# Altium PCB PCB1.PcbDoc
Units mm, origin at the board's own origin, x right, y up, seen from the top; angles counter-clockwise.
Board outline 46 x 20 mm, 2 copper layers (Top Layer, Bottom Layer), stack 1.57 mm thick; 25 components, 17 nets, 41 pads, 5 vias.
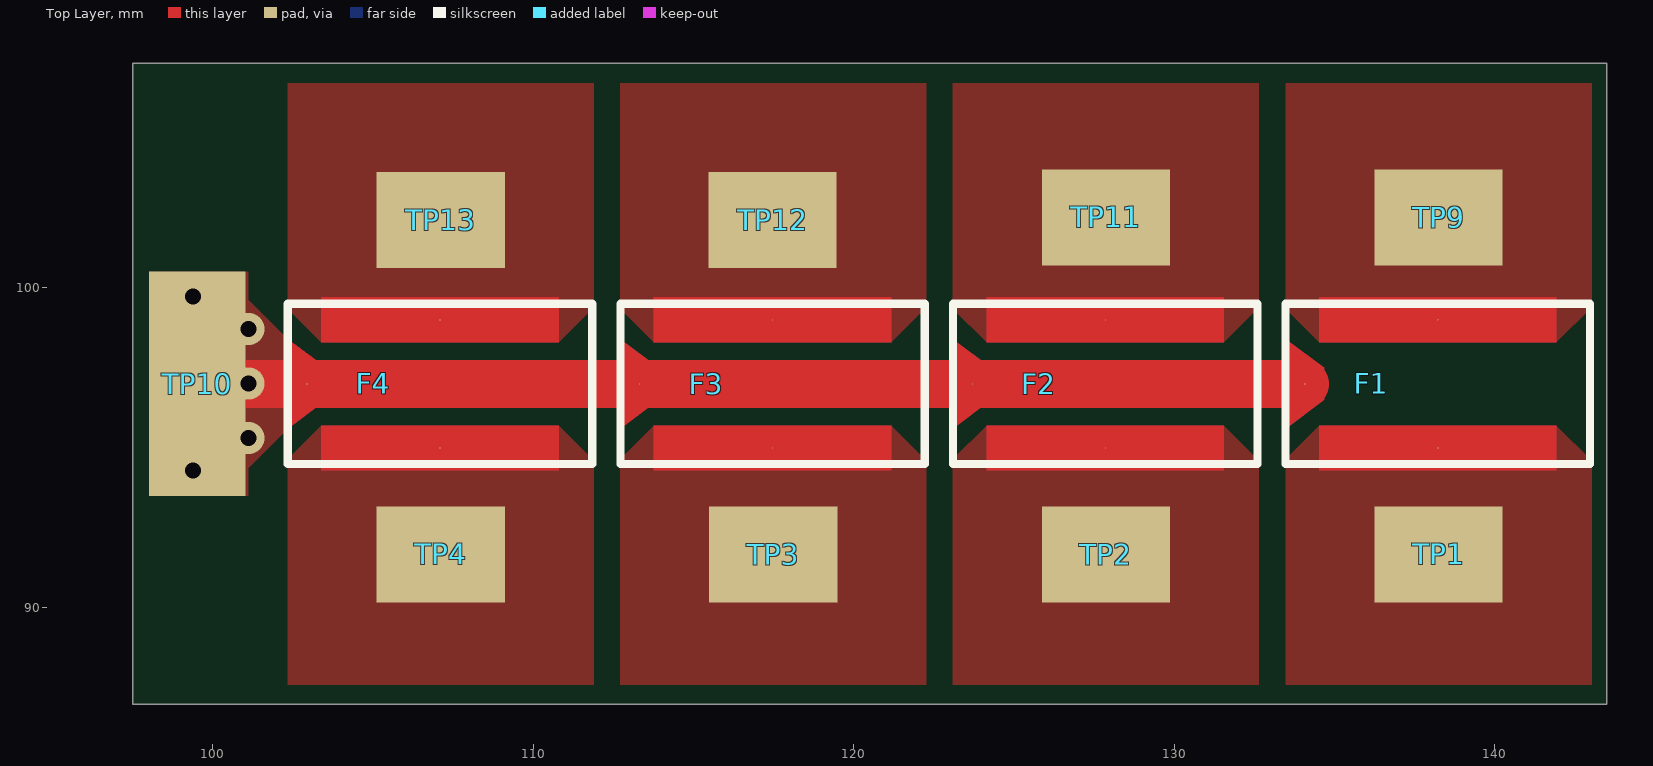
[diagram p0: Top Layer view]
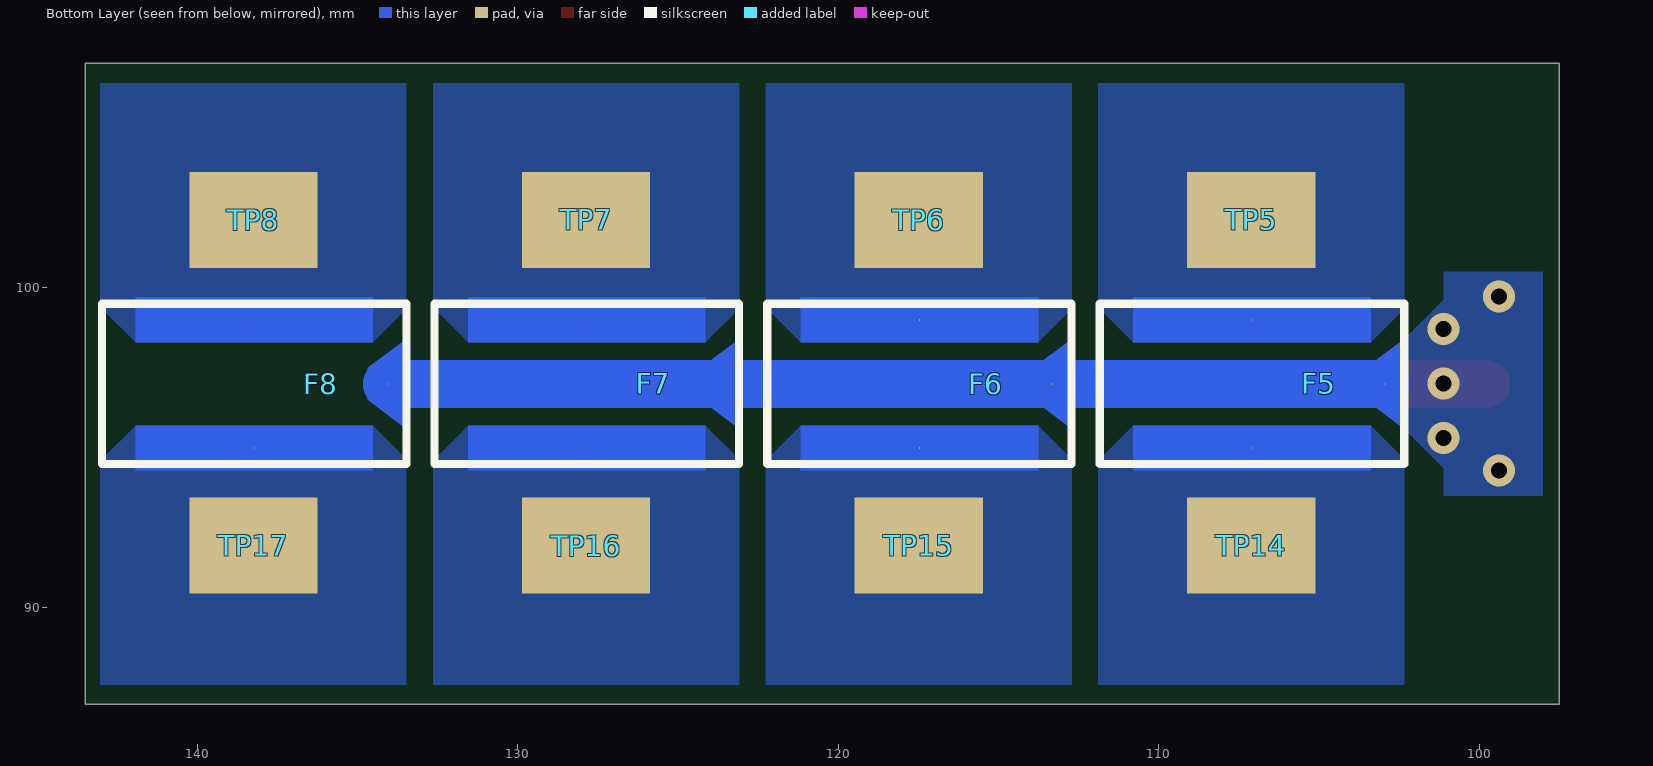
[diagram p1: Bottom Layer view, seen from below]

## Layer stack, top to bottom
Top Solder: solder mask 0.0102, Solder Resist, Dk 3.5
Top Layer: signal copper 0.035
Dielectric 1: core 1.5, FR-4, Dk 4.8
Bottom Layer: signal copper 0.035
Bottom Solder: solder mask 0.0102, Solder Resist, Dk 3.5

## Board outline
97.5,87 97.5,107 143.5,107 143.5,87

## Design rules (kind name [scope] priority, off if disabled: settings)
Clearance [All] p1: gap=0.254 ignorepadtopadclearanceinfootprint=FALSE except(0: Arc-Hole Track-Hole SMDPad-Hole THPad-Hole Via-Hole Fill-Hole Poly-Hole Region-Hole Text-Hole)
MinimumSolderMaskSliver [All] p1: minsoldermaskwidth=0
PolygonConnect [All] p1: connectstyle=Direct reliefconductorwidth=0.254 reliefentries=4 polygonreliefangle="90 Angle" airgapwidth=0.254
RoutingVias [All] p1: holewidth=0.5 width=1 viastyle="Through Hole" minholewidth=0.5 minwidth=1 maxholewidth=0.5 maxwidth=1
SilkToSilkClearance [All] p1: silktosilkclearance=0.127
SilkToSolderMaskClearance [IsPad] p1: minsilkscreentomaskgap=0 clearancetoexposedcopper=TRUE
SolderMaskExpansion [All] p1: expansion=0.102 istentingtop=FALSE
UnRoutedNet [All] p1: checkbadconnections=TRUE
Width [All] p1: maxlimit=5 minlimit=0.254 preferedwidth=0.254 minimp=50.000000 maximp=50.000000 favimp=50.000000
26 further rules are at their usual default settings.

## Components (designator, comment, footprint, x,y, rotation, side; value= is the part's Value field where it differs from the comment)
F1 "SCP60A4K" SCP60a4k 138.225,96.99 r0 top
F2 "SCP60A4K" SCP60a4k 127.846,96.99 r0 top
F3 "SCP60A4K" SCP60a4k 117.468,96.99 r0 top
F4 "SCP60A4K" SCP60a4k 107.089,96.99 r0 top
F5 "SCP60A4K" SCP60a4k 107.089,96.99 r0 bottom
F6 "SCP60A4K" SCP60a4k 117.468,96.99 r0 bottom
F7 "SCP60A4K" SCP60a4k 127.846,96.99 r0 bottom
F8 "SCP60A4K" SCP60a4k 138.225,96.99 r0 bottom
TP1 "3x4mm Test Pad SMD" "3x4mm Test Pad SMD" 138.248,91.669 r90 top
TP2 "3x4mm Test Pad SMD" "3x4mm Test Pad SMD" 127.869,91.669 r90 top
TP3 "3x4mm Test Pad SMD" "3x4mm Test Pad SMD" 117.49,91.669 r90 top
TP4 "3x4mm Test Pad SMD" "3x4mm Test Pad SMD" 107.112,91.669 r90 top
TP5 "3x4mm Test Pad SMD" "3x4mm Test Pad SMD" 107.112,102.108 r270 bottom
TP6 "3x4mm Test Pad SMD" "3x4mm Test Pad SMD" 117.49,102.108 r270 bottom
TP7 "3x4mm Test Pad SMD" "3x4mm Test Pad SMD" 127.869,102.108 r270 bottom
TP8 "3x4mm Test Pad SMD" "3x4mm Test Pad SMD" 138.248,102.108 r270 bottom
TP9 "3x4mm Test Pad SMD" "3x4mm Test Pad SMD" 138.248,102.184 r90 top
TP10 "10X10MM TEST PAD SMD" "10X10MM TEST PAD SMD" 99.517,96.997 r270 top
TP11 "3x4mm Test Pad SMD" "3x4mm Test Pad SMD" 127.869,102.184 r90 top
TP12 "3x4mm Test Pad SMD" "3x4mm Test Pad SMD" 117.468,102.108 r90 top
TP13 "3x4mm Test Pad SMD" "3x4mm Test Pad SMD" 107.112,102.108 r90 top
TP14 "3x4mm Test Pad SMD" "3x4mm Test Pad SMD" 107.112,91.948 r90 bottom
TP15 "3x4mm Test Pad SMD" "3x4mm Test Pad SMD" 117.49,91.948 r270 bottom
TP16 "3x4mm Test Pad SMD" "3x4mm Test Pad SMD" 127.869,91.948 r270 bottom
TP17 "3x4mm Test Pad SMD" "3x4mm Test Pad SMD" 138.248,91.948 r270 bottom

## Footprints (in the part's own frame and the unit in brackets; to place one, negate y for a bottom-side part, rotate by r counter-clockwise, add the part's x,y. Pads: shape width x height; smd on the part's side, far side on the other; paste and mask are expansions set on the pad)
"3x4mm Test Pad SMD" [mm]
  rect 3x4 smd: 1(0,0)
"10X10MM TEST PAD SMD" [mm]
  rect 7x3 smd: 1(0,0)
SCP60a4k [mil]
  round 1 smd: 1(0,78.71) 2(-163.39,0) 3(0,-78.71)
  Top Layer region: -145.67,51.15 -145.67,106.27 145.67,106.27 145.67,51.15
  Top Layer region: -145.67,-106.27 145.67,-106.27 145.67,-51.15 -145.67,-51.15
  Top Layer region: -187.01,-55.12 -139.76,-19.68 -139.76,19.68 -187.01,55.12
  silkscreen extent -187,-98 187,98, body extent -187,-98 187,98, height 79

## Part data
F1 F2 F3 F4 F5 F6 F7 F8: "Self Control Protector"

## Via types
v1: diameter 1, hole 0.5, Top Layer to Bottom Layer, 5 vias

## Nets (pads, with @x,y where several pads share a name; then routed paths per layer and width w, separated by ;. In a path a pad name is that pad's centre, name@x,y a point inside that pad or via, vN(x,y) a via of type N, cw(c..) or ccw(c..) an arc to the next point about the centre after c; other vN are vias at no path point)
NetF1_1: F1.1 TP9.1
NetF1_2: F1.2 F2.2 F3.2 F4.2 F5.2 F6.2 F7.2 F8.2 TP10.1 | length 65.4
  Top Layer w1.5: TP10.1@99.771,96.99 F3.2 114.318,96.99 F2.2 F1.2
  Bottom Layer w1.5: F5.2 F6.2 F8.2
  other v1: 99.39,94.289 101.112,95.299 101.112,97.005 101.112,98.71 99.39,99.72
NetF1_3: F1.3 TP1.1
NetF2_1: F2.1 TP11.1
NetF2_3: F2.3 TP2.1
NetF3_1: F3.1 TP12.1
NetF3_3: F3.3 TP3.1
NetF4_1: F4.1 TP13.1
NetF4_3: F4.3 TP4.1
NetF5_1: F5.1 TP14.1
NetF5_3: F5.3 TP5.1
NetF6_1: F6.1 TP15.1
NetF6_3: F6.3 TP6.1
NetF7_1: F7.1 TP16.1
NetF7_3: F7.3 TP7.1
NetF8_1: F8.1 TP17.1
NetF8_3: F8.3 TP8.1

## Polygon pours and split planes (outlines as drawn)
NetF4_1 on Top Layer "NONET_L-01_P-001" (solid, pour order 48): 103.389,98.289 102.337,99.342 102.337,106.375 111.887,106.375 111.887,99.387 110.789,98.289
NetF1_3 on Top Layer "NONET_L-01_P-001" (solid, pour order 47): 134.525,95.691 133.473,94.638 133.473,87.605 143.023,87.605 143.023,94.593 141.925,95.691
NetF2_3 on Top Layer "NONET_L-01_P-001" (solid, pour order 46): 124.146,95.691 123.094,94.638 123.094,87.605 132.644,87.605 132.644,94.593 131.546,95.691
NetF3_3 on Top Layer "NONET_L-01_P-001" (solid, pour order 45): 113.768,95.691 112.715,94.638 112.715,87.605 122.266,87.605 122.266,94.593 121.168,95.691
NetF4_3 on Top Layer "NONET_L-01_P-001" (solid, pour order 44): 103.389,95.691 102.337,94.638 102.337,87.605 111.887,87.605 111.887,94.593 110.789,95.691
NetF1_1 on Top Layer "NONET_L-01_P-001" (solid, pour order 43): 134.525,98.289 133.473,99.342 133.473,106.375 143.023,106.375 143.023,99.387 141.925,98.289
NetF2_1 on Top Layer "NONET_L-01_P-001" (solid, pour order 42): 124.146,98.289 123.094,99.342 123.094,106.375 132.644,106.375 132.644,99.387 131.546,98.289
NetF3_1 on Top Layer "NONET_L-01_P-001" (solid, pour order 41): 113.768,98.289 112.715,99.342 112.715,106.375 122.266,106.375 122.266,99.387 121.168,98.289
NetF1_2 on Top Layer "NONET_L-01_P-001" (solid, pour order 23): 103.214,97.734 102.339,98.39 101.112,99.617 101.112,100.497 98.017,100.497 98.017,93.497 101.112,93.497 101.112,94.366 102.337,95.59 103.208,96.242 103.208,97.73 103.219,97.73
NetF8_1 on Bottom Layer "NONET_L-01_P-001" (solid, pour order 55): 134.525,95.691 133.473,94.638 133.473,87.605 143.023,87.605 143.023,94.593 141.925,95.691
NetF7_1 on Bottom Layer "NONET_L-01_P-001" (solid, pour order 54): 124.146,95.691 123.094,94.638 123.094,87.605 132.644,87.605 132.644,94.593 131.546,95.691
NetF6_1 on Bottom Layer "NONET_L-01_P-001" (solid, pour order 53): 113.768,95.691 112.715,94.638 112.715,87.605 122.266,87.605 122.266,94.593 121.168,95.691
NetF5_1 on Bottom Layer "NONET_L-01_P-001" (solid, pour order 52): 103.389,95.691 102.337,94.638 102.337,87.605 111.887,87.605 111.887,94.593 110.789,95.691
NetF8_3 on Bottom Layer "NONET_L-01_P-001" (solid, pour order 51): 134.525,98.289 133.473,99.342 133.473,106.375 143.023,106.375 143.023,99.387 141.925,98.289
NetF7_3 on Bottom Layer "NONET_L-01_P-001" (solid, pour order 50): 124.146,98.289 123.094,99.342 123.094,106.375 132.644,106.375 132.644,99.387 131.546,98.289
NetF6_3 on Bottom Layer "NONET_L-01_P-001" (solid, pour order 49): 113.768,98.289 112.715,99.342 112.715,106.375 122.266,106.375 122.266,99.387 121.168,98.289
NetF5_3 on Bottom Layer "NONET_L-01_P-001" (solid, pour order 26): 103.389,98.289 102.337,99.342 102.337,106.375 111.887,106.375 111.887,99.387 110.789,98.289
NetF1_2 on Bottom Layer "NONET_L-01_P-001" (solid, pour order 22): 103.214,97.734 102.339,98.39 101.112,99.617 101.112,100.497 98.019,100.497 98.019,93.497 101.112,93.497 101.112,94.366 102.337,95.59 103.208,96.242 103.208,97.73 103.219,97.73
no net on Bottom Solder "NONET_L-01_P-001" (solid): 142.063,95.707 142.063,94.361 143.028,93.396 143.028,87.605 133.478,87.605 133.478,93.371 134.468,94.361 134.468,95.707
no net on Bottom Solder "NONET_L-01_P-001" (solid): 134.438,98.273 134.438,99.619 133.473,100.584 133.473,106.375 143.023,106.375 143.023,100.609 142.032,99.619 142.032,98.273
no net on Bottom Solder "NONET_L-01_P-001" (solid): 124.059,98.273 124.059,99.619 123.094,100.584 123.094,106.375 132.644,106.375 132.644,100.609 131.654,99.619 131.654,98.273
no net on Bottom Solder "NONET_L-01_P-001" (solid): 113.68,98.273 113.68,99.619 112.715,100.584 112.715,106.375 122.266,106.375 122.266,100.609 121.275,99.619 121.275,98.273
no net on Bottom Solder "NONET_L-01_P-001" (solid): 103.302,98.273 103.302,99.619 102.337,100.584 102.337,106.375 111.887,106.375 111.887,100.609 110.896,99.619 110.896,98.273
no net on Bottom Solder "NONET_L-01_P-001" (solid): 110.927,95.707 110.927,94.361 111.892,93.396 111.892,87.605 102.342,87.605 102.342,93.371 103.332,94.361 103.332,95.707
no net on Bottom Solder "NONET_L-01_P-001" (solid): 121.306,95.707 121.306,94.361 122.271,93.396 122.271,87.605 112.72,87.605 112.72,93.371 113.711,94.361 113.711,95.707
no net on Bottom Solder "NONET_L-01_P-001" (solid): 131.684,95.707 131.684,94.361 132.65,93.396 132.65,87.605 123.099,87.605 123.099,93.371 124.09,94.361 124.09,95.707
no net on Bottom Solder "NONET_L-01_P-001" (solid): 101.112,100.497 101.112,99.599 102.337,98.374 102.337,95.606 101.112,94.381 101.112,93.497 98.019,93.497 98.019,100.497
no net on Top Solder "NONET_L-01_P-001" (solid): 103.302,98.273 103.302,99.619 102.337,100.584 102.337,106.375 111.887,106.375 111.887,100.609 110.896,99.619 110.896,98.273
no net on Top Solder "NONET_L-01_P-001" (solid): 113.68,98.273 113.68,99.619 112.715,100.584 112.715,106.375 122.266,106.375 122.266,100.609 121.275,99.619 121.275,98.273
no net on Top Solder "NONET_L-01_P-001" (solid): 124.059,98.273 124.059,99.619 123.094,100.584 123.094,106.375 132.644,106.375 132.644,100.609 131.654,99.619 131.654,98.273
no net on Top Solder "NONET_L-01_P-001" (solid): 134.438,98.273 134.438,99.619 133.473,100.584 133.473,106.375 143.023,106.375 143.023,100.609 142.032,99.619 142.032,98.273
no net on Top Solder "NONET_L-01_P-001" (solid): 142.063,95.707 142.063,94.361 143.028,93.396 143.028,87.605 133.478,87.605 133.478,93.371 134.468,94.361 134.468,95.707
no net on Top Solder "NONET_L-01_P-001" (solid): 131.684,95.707 131.684,94.361 132.65,93.396 132.65,87.605 123.099,87.605 123.099,93.371 124.09,94.361 124.09,95.707
no net on Top Solder "NONET_L-01_P-001" (solid): 121.306,95.707 121.306,94.361 122.271,93.396 122.271,87.605 112.72,87.605 112.72,93.371 113.711,94.361 113.711,95.707
no net on Top Solder "NONET_L-01_P-001" (solid): 110.927,95.707 110.927,94.361 111.892,93.396 111.892,87.605 102.342,87.605 102.342,93.371 103.332,94.361 103.332,95.707
NetF1_2 on Top Solder "NONET_L-01_P-001" (solid, pour order 40): 101.112,100.497 101.112,99.599 102.337,98.374 102.337,95.606 101.112,94.381 101.112,93.497 98.044,93.497 98.044,100.497

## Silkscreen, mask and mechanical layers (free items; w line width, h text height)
Board Outline:
  the board outline again, w0.178
Fab:
  drawing of 191 lines, arcs and shapes, not listed
  text "Layer" at 155.385,105.512 h1.52
  text "Name" at 165.796,105.512 h1.52
  text "Material" at 189.412,105.512 h1.52
  text "Thickness" at 211.25,105.512 h1.52
  text "Constant" at 227.756,105.512 h1.52
  text "Board Layer Stack" at 242.23,105.512 h1.52
  text "Top Overlay" at 165.796,102.464 h1.52
  text "Top Solder" at 165.796,99.416 h1.52
  text "Solder Resist" at 189.412,99.416 h1.52
  text "0.010mm" at 211.25,99.416 h1.52
  text "3.5" at 227.756,99.416 h1.52
  text "1" at 155.385,96.368 h1.52
  text "Top Layer" at 165.796,96.368 h1.52
  text "0.035mm" at 211.25,96.368 h1.52
  text "Dielectric 1" at 165.796,93.32 h1.52
  text "FR-4" at 189.412,93.32 h1.52
  text "1.500mm" at 211.25,93.32 h1.52
  text "4.8" at 227.756,93.32 h1.52
  text "2" at 155.385,90.272 h1.52
  text "Bottom Layer" at 165.796,90.272 h1.52
  text "0.035mm" at 211.25,90.272 h1.52
  text "Bottom Solder" at 165.796,87.224 h1.52
  text "Solder Resist" at 189.412,87.224 h1.52
  text "0.010mm" at 211.25,87.224 h1.52
  text "3.5" at 227.756,87.224 h1.52
  text "Bottom Overlay" at 165.796,84.176 h1.52
  text "Total board thickness:" at 155.385,81.128 h1.52
  text "1.590mm" at 211.25,81.128 h1.52
Drill Drawing:
  lines w0.254: 95.41,115.354 97.103,115.354 97.103,117.047 95.41,117.047 95.41,115.354
  lines w0.381: 93.891,114.211 268.901,114.211 ; 93.891,118.021 268.901,118.021 ; 107.883,110.401 107.883,121.831 ; 120.072,110.401 120.072,121.831 ; 147.75,110.401 147.75,121.831 ; 160.599,110.401 160.599,121.831 ; 179.238,110.401 179.238,121.831 ; 217.327,110.401 217.327,121.831 ; 232.309,110.401 232.309,121.831 ; 251.252,110.401 251.252,121.831 ; 93.891,110.401 268.901,110.401 268.901,121.831 93.891,121.831 93.891,110.401
  text "Symbol" at 96.177,119.164 h1.83
  text "Count" at 109.026,119.164 h1.83
  text "Hole Size" at 121.215,119.164 h1.83
  text "Plated" at 148.893,119.164 h1.83
  text "Hole Type" at 161.742,119.164 h1.83
  text "Drill Layer Pair" at 180.381,119.164 h1.83
  text "Via/Pad" at 218.47,119.164 h1.83
  text "Pad Shape" at 233.452,119.164 h1.83
  text "Template" at 252.395,119.164 h1.83
  text "5" at 109.026,115.354 h1.52
  text "0.500mm (19.69mil)" at 121.215,115.354 h1.52
  text "PTH" at 148.893,115.354 h1.52
  text "Round" at 161.742,115.354 h1.52
  text "Top Layer - Bottom Layer" at 180.381,115.354 h1.52
  text "Via" at 218.47,115.354 h1.52
  text "Rounded" at 233.452,115.354 h1.52
  text "v100h50" at 252.395,115.354 h1.52
  text "5 Total" at 109.026,111.544 h1.52

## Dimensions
143.5,107 to 143.5,87 on Mechanical 1
97.5,107 to 143.5,107 on Mechanical 1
